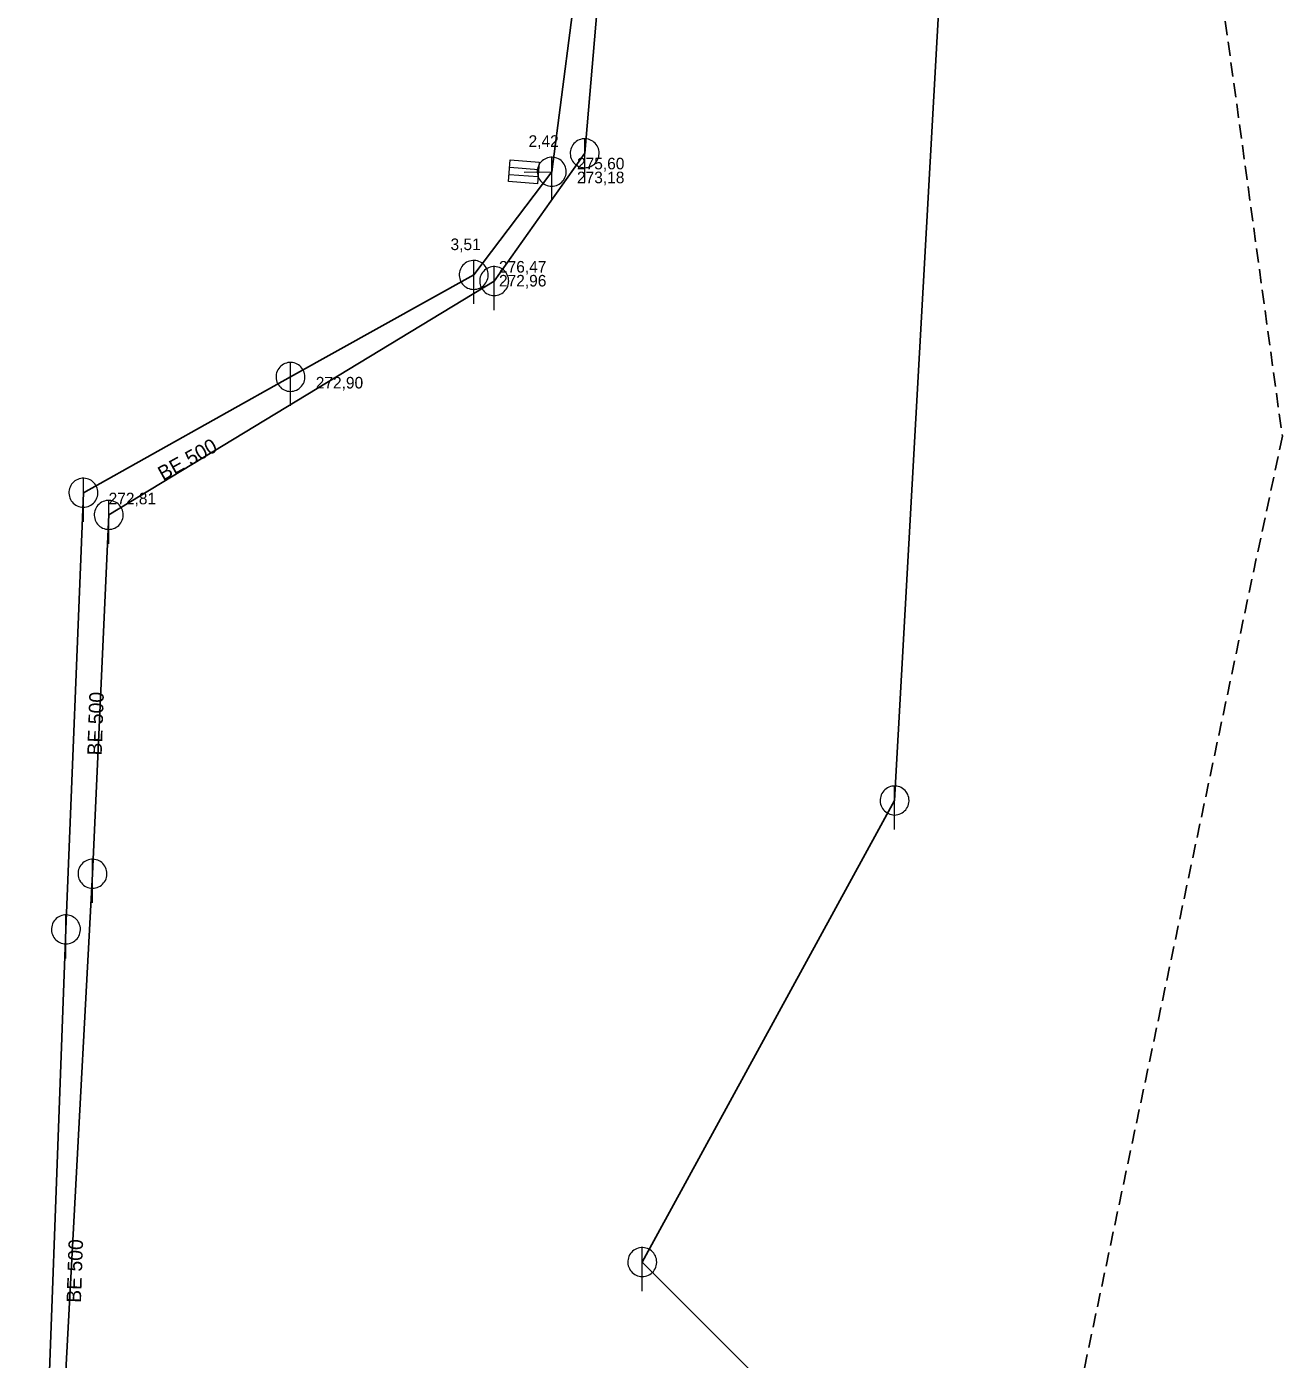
# Model space of a CAD drawing. Extents: x -725153 to -724843, y -978146 to -977794.
# Drawn here: x -724929.4 to -724842.7, y -977983.1 to -977891.1 of the extents above; entities that cross this region are included whole.
import ezdxf

# ---------------------------------------------------------------- set-up
doc = ezdxf.new("R2010")
doc.units = 0
doc.header["$LTSCALE"] = 0.32
doc.linetypes.add('MEDIUM_DASHED', pattern=[4.5, 3, -1.5])
doc.layers.add('1', color=7, linetype='Continuous')
for name, color, linetype, lineweight in [('11', 7, 'Continuous', 13), ('14', 7, 'Continuous', 25), ('22', 7, 'Continuous', 13), ('63', 7, 'MEDIUM_DASHED', 25)]:
    doc.layers.add(name, color=color, linetype=linetype, lineweight=lineweight)

msp = doc.modelspace()

# ---------------------------------------------------------------- linework, layer by layer
at = {"layer": '11'}
msp.add_line((-724895.067, -977901.119), (-724893.153, -977901.096), dxfattribs=at)
at = {"layer": '14'}
for p, q in [((-724887.943, -977865.316), (-724890.881, -977899.822)), ((-724890.881, -977899.822), (-724897.126, -977908.645)), ((-724893.153, -977901.096), (-724898.538, -977908.222)), ((-724897.126, -977908.645), (-724923.729, -977924.789)), ((-724898.538, -977908.222), (-724911.184, -977915.262)), ((-724911.184, -977915.262), (-724925.479, -977923.259)), ((-724925.479, -977923.259), (-724926.682, -977953.405)), ((-724923.729, -977924.789), (-724924.849, -977949.559))]:
    msp.add_line(p, q, dxfattribs=at)
for points in [[(-724873.038, -977838.517), (-724866.293, -977887.198), (-724869.492, -977944.507)], [(-724888.955, -977868.761), (-724891.145, -977885.63), (-724893.153, -977901.096)], [(-724869.492, -977944.507), (-724886.907, -977976.368), (-724871.886, -977991.369), (-724874.269, -978025.195)], [(-724924.849, -977949.559), (-724927.569, -978000.189), (-724927.274, -978049.14)], [(-724926.682, -977953.405), (-724928.359, -977998.839), (-724927.944, -978048.326)]]:
    msp.add_lwpolyline(points, dxfattribs=at)
at = {"layer": '22'}
for p, q in [((-724890.881, -977901.822), (-724890.88, -977898.822)), ((-724893.153, -977903.096), (-724893.152, -977900.096)), ((-724896.093, -977901.286), (-724894.098, -977901.435)), ((-724896.056, -977900.787), (-724894.061, -977900.936)), ((-724898.538, -977910.222), (-724898.537, -977907.222)), ((-724897.126, -977910.645), (-724897.125, -977907.645)), ((-724911.184, -977917.262), (-724911.183, -977914.262)), ((-724925.479, -977925.259), (-724925.478, -977922.259)), ((-724923.729, -977926.789), (-724923.728, -977923.789)), ((-724869.492, -977946.507), (-724869.491, -977943.507)), ((-724924.849, -977951.559), (-724924.848, -977948.559)), ((-724926.682, -977955.405), (-724926.681, -977952.405)), ((-724886.907, -977978.368), (-724886.906, -977975.368))]:
    msp.add_line(p, q, dxfattribs=at)
for points in [[(-724889.881, -977899.822), (-724889.886, -977899.713), (-724889.904, -977899.605), (-724889.934, -977899.499), (-724889.974, -977899.398), (-724890.026, -977899.301), (-724890.088, -977899.211), (-724890.16, -977899.128), (-724890.24, -977899.054), (-724890.328, -977898.988), (-724890.422, -977898.933), (-724890.522, -977898.888), (-724890.627, -977898.855), (-724890.734, -977898.833), (-724890.843, -977898.823), (-724890.953, -977898.825), (-724891.061, -977898.839), (-724891.168, -977898.864), (-724891.271, -977898.901), (-724891.369, -977898.95), (-724891.461, -977899.008), (-724891.547, -977899.077), (-724891.624, -977899.154), (-724891.693, -977899.24), (-724891.752, -977899.332), (-724891.8, -977899.43), (-724891.837, -977899.533), (-724891.863, -977899.64), (-724891.877, -977899.748), (-724891.88, -977899.858), (-724891.87, -977899.967), (-724891.849, -977900.074), (-724891.815, -977900.178), (-724891.771, -977900.278), (-724891.716, -977900.373), (-724891.65, -977900.461), (-724891.576, -977900.541), (-724891.493, -977900.613), (-724891.403, -977900.675), (-724891.307, -977900.727), (-724891.205, -977900.768), (-724891.1, -977900.798), (-724890.992, -977900.816), (-724890.882, -977900.822), (-724890.773, -977900.816), (-724890.665, -977900.798), (-724890.56, -977900.769), (-724890.458, -977900.728), (-724890.361, -977900.676), (-724890.271, -977900.614), (-724890.188, -977900.543), (-724890.113, -977900.463), (-724890.048, -977900.375), (-724889.992, -977900.281), (-724889.948, -977900.181), (-724889.914, -977900.077), (-724889.892, -977899.969), (-724889.882, -977899.86)], [(-724896.018, -977900.289), (-724894.024, -977900.438), (-724894.136, -977901.934), (-724896.13, -977901.785)], [(-724892.153, -977901.096), (-724892.158, -977900.987), (-724892.176, -977900.879), (-724892.206, -977900.773), (-724892.246, -977900.672), (-724892.298, -977900.575), (-724892.36, -977900.485), (-724892.432, -977900.402), (-724892.512, -977900.328), (-724892.6, -977900.262), (-724892.694, -977900.207), (-724892.794, -977900.162), (-724892.899, -977900.129), (-724893.006, -977900.107), (-724893.115, -977900.097), (-724893.225, -977900.099), (-724893.333, -977900.113), (-724893.44, -977900.138), (-724893.543, -977900.175), (-724893.641, -977900.224), (-724893.733, -977900.282), (-724893.819, -977900.351), (-724893.896, -977900.428), (-724893.965, -977900.514), (-724894.024, -977900.606), (-724894.072, -977900.704), (-724894.109, -977900.807), (-724894.135, -977900.914), (-724894.149, -977901.022), (-724894.152, -977901.132), (-724894.142, -977901.241), (-724894.121, -977901.348), (-724894.087, -977901.452), (-724894.043, -977901.552), (-724893.988, -977901.647), (-724893.922, -977901.735), (-724893.848, -977901.815), (-724893.765, -977901.887), (-724893.675, -977901.949), (-724893.579, -977902.001), (-724893.477, -977902.042), (-724893.372, -977902.072), (-724893.264, -977902.09), (-724893.154, -977902.096), (-724893.045, -977902.09), (-724892.937, -977902.072), (-724892.832, -977902.043), (-724892.73, -977902.002), (-724892.633, -977901.95), (-724892.543, -977901.888), (-724892.46, -977901.817), (-724892.385, -977901.737), (-724892.32, -977901.649), (-724892.264, -977901.555), (-724892.22, -977901.455), (-724892.186, -977901.351), (-724892.164, -977901.243), (-724892.154, -977901.134)], [(-724897.538, -977908.222), (-724897.543, -977908.113), (-724897.561, -977908.005), (-724897.591, -977907.899), (-724897.631, -977907.798), (-724897.683, -977907.701), (-724897.745, -977907.611), (-724897.817, -977907.528), (-724897.897, -977907.454), (-724897.985, -977907.388), (-724898.079, -977907.333), (-724898.179, -977907.288), (-724898.284, -977907.255), (-724898.391, -977907.233), (-724898.5, -977907.223), (-724898.61, -977907.225), (-724898.718, -977907.239), (-724898.825, -977907.264), (-724898.928, -977907.301), (-724899.026, -977907.35), (-724899.118, -977907.408), (-724899.204, -977907.477), (-724899.281, -977907.554), (-724899.35, -977907.64), (-724899.409, -977907.732), (-724899.457, -977907.83), (-724899.494, -977907.933), (-724899.52, -977908.04), (-724899.534, -977908.148), (-724899.537, -977908.258), (-724899.527, -977908.367), (-724899.506, -977908.474), (-724899.472, -977908.578), (-724899.428, -977908.678), (-724899.373, -977908.773), (-724899.307, -977908.861), (-724899.233, -977908.941), (-724899.15, -977909.013), (-724899.06, -977909.075), (-724898.964, -977909.127), (-724898.862, -977909.168), (-724898.757, -977909.198), (-724898.649, -977909.216), (-724898.539, -977909.222), (-724898.43, -977909.216), (-724898.322, -977909.198), (-724898.217, -977909.169), (-724898.115, -977909.128), (-724898.018, -977909.076), (-724897.928, -977909.014), (-724897.845, -977908.943), (-724897.77, -977908.863), (-724897.705, -977908.775), (-724897.649, -977908.681), (-724897.605, -977908.581), (-724897.571, -977908.477), (-724897.549, -977908.369), (-724897.539, -977908.26)], [(-724896.126, -977908.645), (-724896.131, -977908.536), (-724896.149, -977908.428), (-724896.179, -977908.322), (-724896.219, -977908.221), (-724896.271, -977908.124), (-724896.333, -977908.034), (-724896.405, -977907.951), (-724896.485, -977907.877), (-724896.573, -977907.811), (-724896.667, -977907.756), (-724896.767, -977907.711), (-724896.872, -977907.678), (-724896.979, -977907.656), (-724897.088, -977907.646), (-724897.198, -977907.648), (-724897.306, -977907.662), (-724897.413, -977907.687), (-724897.516, -977907.724), (-724897.614, -977907.773), (-724897.706, -977907.831), (-724897.792, -977907.9), (-724897.869, -977907.977), (-724897.938, -977908.063), (-724897.997, -977908.155), (-724898.045, -977908.253), (-724898.082, -977908.356), (-724898.108, -977908.463), (-724898.122, -977908.571), (-724898.125, -977908.681), (-724898.115, -977908.79), (-724898.094, -977908.897), (-724898.06, -977909.001), (-724898.016, -977909.101), (-724897.961, -977909.196), (-724897.895, -977909.284), (-724897.821, -977909.364), (-724897.738, -977909.436), (-724897.648, -977909.498), (-724897.552, -977909.55), (-724897.45, -977909.591), (-724897.345, -977909.621), (-724897.237, -977909.639), (-724897.127, -977909.645), (-724897.018, -977909.639), (-724896.91, -977909.621), (-724896.805, -977909.592), (-724896.703, -977909.551), (-724896.606, -977909.499), (-724896.516, -977909.437), (-724896.433, -977909.366), (-724896.358, -977909.286), (-724896.293, -977909.198), (-724896.237, -977909.104), (-724896.193, -977909.004), (-724896.159, -977908.9), (-724896.137, -977908.792), (-724896.127, -977908.683)], [(-724910.184, -977915.262), (-724910.189, -977915.153), (-724910.207, -977915.045), (-724910.237, -977914.939), (-724910.277, -977914.838), (-724910.329, -977914.741), (-724910.391, -977914.651), (-724910.463, -977914.568), (-724910.543, -977914.494), (-724910.631, -977914.428), (-724910.725, -977914.373), (-724910.825, -977914.328), (-724910.93, -977914.295), (-724911.037, -977914.273), (-724911.146, -977914.263), (-724911.256, -977914.265), (-724911.364, -977914.279), (-724911.471, -977914.304), (-724911.574, -977914.341), (-724911.672, -977914.39), (-724911.764, -977914.448), (-724911.85, -977914.517), (-724911.927, -977914.594), (-724911.996, -977914.68), (-724912.055, -977914.772), (-724912.103, -977914.87), (-724912.14, -977914.973), (-724912.166, -977915.08), (-724912.18, -977915.188), (-724912.183, -977915.298), (-724912.173, -977915.407), (-724912.152, -977915.514), (-724912.118, -977915.618), (-724912.074, -977915.718), (-724912.019, -977915.813), (-724911.953, -977915.901), (-724911.879, -977915.981), (-724911.796, -977916.053), (-724911.706, -977916.115), (-724911.61, -977916.167), (-724911.508, -977916.208), (-724911.403, -977916.238), (-724911.295, -977916.256), (-724911.185, -977916.262), (-724911.076, -977916.256), (-724910.968, -977916.238), (-724910.863, -977916.209), (-724910.761, -977916.168), (-724910.664, -977916.116), (-724910.574, -977916.054), (-724910.491, -977915.983), (-724910.416, -977915.903), (-724910.351, -977915.815), (-724910.295, -977915.721), (-724910.251, -977915.621), (-724910.217, -977915.517), (-724910.195, -977915.409), (-724910.185, -977915.3)], [(-724924.479, -977923.259), (-724924.484, -977923.15), (-724924.502, -977923.042), (-724924.532, -977922.936), (-724924.572, -977922.835), (-724924.624, -977922.738), (-724924.686, -977922.648), (-724924.758, -977922.565), (-724924.838, -977922.491), (-724924.926, -977922.425), (-724925.02, -977922.37), (-724925.12, -977922.325), (-724925.225, -977922.292), (-724925.332, -977922.27), (-724925.441, -977922.26), (-724925.551, -977922.262), (-724925.659, -977922.276), (-724925.766, -977922.301), (-724925.869, -977922.338), (-724925.967, -977922.387), (-724926.059, -977922.445), (-724926.145, -977922.514), (-724926.222, -977922.591), (-724926.291, -977922.677), (-724926.35, -977922.769), (-724926.398, -977922.867), (-724926.435, -977922.97), (-724926.461, -977923.077), (-724926.475, -977923.185), (-724926.478, -977923.295), (-724926.468, -977923.404), (-724926.447, -977923.511), (-724926.413, -977923.615), (-724926.369, -977923.715), (-724926.314, -977923.81), (-724926.248, -977923.898), (-724926.174, -977923.978), (-724926.091, -977924.05), (-724926.001, -977924.112), (-724925.905, -977924.164), (-724925.803, -977924.205), (-724925.698, -977924.235), (-724925.59, -977924.253), (-724925.48, -977924.259), (-724925.371, -977924.253), (-724925.263, -977924.235), (-724925.158, -977924.206), (-724925.056, -977924.165), (-724924.959, -977924.113), (-724924.869, -977924.051), (-724924.786, -977923.98), (-724924.711, -977923.9), (-724924.646, -977923.812), (-724924.59, -977923.718), (-724924.546, -977923.618), (-724924.512, -977923.514), (-724924.49, -977923.406), (-724924.48, -977923.297)], [(-724922.729, -977924.789), (-724922.734, -977924.68), (-724922.752, -977924.572), (-724922.782, -977924.466), (-724922.822, -977924.365), (-724922.874, -977924.268), (-724922.936, -977924.178), (-724923.008, -977924.095), (-724923.088, -977924.021), (-724923.176, -977923.955), (-724923.27, -977923.9), (-724923.37, -977923.855), (-724923.475, -977923.822), (-724923.582, -977923.8), (-724923.691, -977923.79), (-724923.801, -977923.792), (-724923.909, -977923.806), (-724924.016, -977923.831), (-724924.119, -977923.868), (-724924.217, -977923.917), (-724924.309, -977923.975), (-724924.395, -977924.044), (-724924.472, -977924.121), (-724924.541, -977924.207), (-724924.6, -977924.299), (-724924.648, -977924.397), (-724924.685, -977924.5), (-724924.711, -977924.607), (-724924.725, -977924.715), (-724924.728, -977924.825), (-724924.718, -977924.934), (-724924.697, -977925.041), (-724924.663, -977925.145), (-724924.619, -977925.245), (-724924.564, -977925.34), (-724924.498, -977925.428), (-724924.424, -977925.508), (-724924.341, -977925.58), (-724924.251, -977925.642), (-724924.155, -977925.694), (-724924.053, -977925.735), (-724923.948, -977925.765), (-724923.84, -977925.783), (-724923.73, -977925.789), (-724923.621, -977925.783), (-724923.513, -977925.765), (-724923.408, -977925.736), (-724923.306, -977925.695), (-724923.209, -977925.643), (-724923.119, -977925.581), (-724923.036, -977925.51), (-724922.961, -977925.43), (-724922.896, -977925.342), (-724922.84, -977925.248), (-724922.796, -977925.148), (-724922.762, -977925.044), (-724922.74, -977924.936), (-724922.73, -977924.827)], [(-724868.492, -977944.507), (-724868.497, -977944.398), (-724868.515, -977944.29), (-724868.545, -977944.184), (-724868.585, -977944.083), (-724868.637, -977943.986), (-724868.699, -977943.896), (-724868.771, -977943.813), (-724868.851, -977943.739), (-724868.939, -977943.673), (-724869.033, -977943.618), (-724869.133, -977943.573), (-724869.238, -977943.54), (-724869.345, -977943.518), (-724869.454, -977943.508), (-724869.564, -977943.51), (-724869.672, -977943.524), (-724869.779, -977943.549), (-724869.882, -977943.586), (-724869.98, -977943.635), (-724870.072, -977943.693), (-724870.158, -977943.762), (-724870.235, -977943.839), (-724870.304, -977943.925), (-724870.363, -977944.017), (-724870.411, -977944.115), (-724870.448, -977944.218), (-724870.474, -977944.325), (-724870.488, -977944.433), (-724870.491, -977944.543), (-724870.481, -977944.652), (-724870.46, -977944.759), (-724870.426, -977944.863), (-724870.382, -977944.963), (-724870.327, -977945.058), (-724870.261, -977945.146), (-724870.187, -977945.226), (-724870.104, -977945.298), (-724870.014, -977945.36), (-724869.918, -977945.412), (-724869.816, -977945.453), (-724869.711, -977945.483), (-724869.603, -977945.501), (-724869.493, -977945.507), (-724869.384, -977945.501), (-724869.276, -977945.483), (-724869.171, -977945.454), (-724869.069, -977945.413), (-724868.972, -977945.361), (-724868.882, -977945.299), (-724868.799, -977945.228), (-724868.724, -977945.148), (-724868.659, -977945.06), (-724868.603, -977944.966), (-724868.559, -977944.866), (-724868.525, -977944.762), (-724868.503, -977944.654), (-724868.493, -977944.545)], [(-724923.849, -977949.559), (-724923.854, -977949.45), (-724923.872, -977949.342), (-724923.902, -977949.236), (-724923.942, -977949.135), (-724923.994, -977949.038), (-724924.056, -977948.948), (-724924.128, -977948.865), (-724924.208, -977948.791), (-724924.296, -977948.725), (-724924.39, -977948.67), (-724924.49, -977948.625), (-724924.595, -977948.592), (-724924.702, -977948.57), (-724924.811, -977948.56), (-724924.921, -977948.562), (-724925.029, -977948.576), (-724925.136, -977948.601), (-724925.239, -977948.638), (-724925.337, -977948.687), (-724925.429, -977948.745), (-724925.515, -977948.814), (-724925.592, -977948.891), (-724925.661, -977948.977), (-724925.72, -977949.069), (-724925.768, -977949.167), (-724925.805, -977949.27), (-724925.831, -977949.377), (-724925.845, -977949.485), (-724925.848, -977949.595), (-724925.838, -977949.704), (-724925.817, -977949.811), (-724925.783, -977949.915), (-724925.739, -977950.015), (-724925.684, -977950.11), (-724925.618, -977950.198), (-724925.544, -977950.278), (-724925.461, -977950.35), (-724925.371, -977950.412), (-724925.275, -977950.464), (-724925.173, -977950.505), (-724925.068, -977950.535), (-724924.96, -977950.553), (-724924.85, -977950.559), (-724924.741, -977950.553), (-724924.633, -977950.535), (-724924.528, -977950.506), (-724924.426, -977950.465), (-724924.329, -977950.413), (-724924.239, -977950.351), (-724924.156, -977950.28), (-724924.081, -977950.2), (-724924.016, -977950.112), (-724923.96, -977950.018), (-724923.916, -977949.918), (-724923.882, -977949.814), (-724923.86, -977949.706), (-724923.85, -977949.597)], [(-724925.682, -977953.405), (-724925.687, -977953.296), (-724925.705, -977953.188), (-724925.735, -977953.082), (-724925.775, -977952.981), (-724925.827, -977952.884), (-724925.889, -977952.794), (-724925.961, -977952.711), (-724926.041, -977952.637), (-724926.129, -977952.571), (-724926.223, -977952.516), (-724926.323, -977952.471), (-724926.428, -977952.438), (-724926.535, -977952.416), (-724926.644, -977952.406), (-724926.754, -977952.408), (-724926.862, -977952.422), (-724926.969, -977952.447), (-724927.072, -977952.484), (-724927.17, -977952.533), (-724927.262, -977952.591), (-724927.348, -977952.66), (-724927.425, -977952.737), (-724927.494, -977952.823), (-724927.553, -977952.915), (-724927.601, -977953.013), (-724927.638, -977953.116), (-724927.664, -977953.223), (-724927.678, -977953.331), (-724927.681, -977953.441), (-724927.671, -977953.55), (-724927.65, -977953.657), (-724927.616, -977953.761), (-724927.572, -977953.861), (-724927.517, -977953.956), (-724927.451, -977954.044), (-724927.377, -977954.124), (-724927.294, -977954.196), (-724927.204, -977954.258), (-724927.108, -977954.31), (-724927.006, -977954.351), (-724926.901, -977954.381), (-724926.793, -977954.399), (-724926.683, -977954.405), (-724926.574, -977954.399), (-724926.466, -977954.381), (-724926.361, -977954.352), (-724926.259, -977954.311), (-724926.162, -977954.259), (-724926.072, -977954.197), (-724925.989, -977954.126), (-724925.914, -977954.046), (-724925.849, -977953.958), (-724925.793, -977953.864), (-724925.749, -977953.764), (-724925.715, -977953.66), (-724925.693, -977953.552), (-724925.683, -977953.443)], [(-724885.907, -977976.368), (-724885.912, -977976.259), (-724885.93, -977976.151), (-724885.96, -977976.045), (-724886, -977975.944), (-724886.052, -977975.847), (-724886.114, -977975.757), (-724886.186, -977975.674), (-724886.266, -977975.6), (-724886.354, -977975.534), (-724886.448, -977975.479), (-724886.548, -977975.434), (-724886.653, -977975.401), (-724886.76, -977975.379), (-724886.869, -977975.369), (-724886.979, -977975.371), (-724887.087, -977975.385), (-724887.194, -977975.41), (-724887.297, -977975.447), (-724887.395, -977975.496), (-724887.487, -977975.554), (-724887.573, -977975.623), (-724887.65, -977975.7), (-724887.719, -977975.786), (-724887.778, -977975.878), (-724887.826, -977975.976), (-724887.863, -977976.079), (-724887.889, -977976.186), (-724887.903, -977976.294), (-724887.906, -977976.404), (-724887.896, -977976.513), (-724887.875, -977976.62), (-724887.841, -977976.724), (-724887.797, -977976.824), (-724887.742, -977976.919), (-724887.676, -977977.007), (-724887.602, -977977.087), (-724887.519, -977977.159), (-724887.429, -977977.221), (-724887.333, -977977.273), (-724887.231, -977977.314), (-724887.126, -977977.344), (-724887.018, -977977.362), (-724886.908, -977977.368), (-724886.799, -977977.362), (-724886.691, -977977.344), (-724886.586, -977977.315), (-724886.484, -977977.274), (-724886.387, -977977.222), (-724886.297, -977977.16), (-724886.214, -977977.089), (-724886.139, -977977.009), (-724886.074, -977976.921), (-724886.018, -977976.827), (-724885.974, -977976.727), (-724885.94, -977976.623), (-724885.918, -977976.515), (-724885.908, -977976.406)]]:
    msp.add_lwpolyline(points, close=True, dxfattribs=at)
at = {"layer": '63'}
msp.add_lwpolyline([(-725126.038, -977904.704), (-725126.038, -977794.451), (-724874.829, -977812.594), (-724855.29, -977827.945), (-724842.73, -977919.358), (-724859.477, -977998.21), (-724911.114, -978092.413), (-724961.356, -978146.144), (-725152.554, -978126.605)], close=True, dxfattribs=at)

# ---------------------------------------------------------------- texts
at = {"layer": '1'}
for s, p in [('2,42', (-724894.753, -977899.384)), ('3,51', (-724900.138, -977906.51))]:
    msp.add_text(s, height=0.8, dxfattribs=at).set_placement(p)
for rotation, p in [(29, (-724919.98, -977922.457)), (88, (-724924.216, -977941.408)), (88, (-724925.646, -977979.192))]:
    msp.add_text('BE 500', height=1, rotation=rotation, dxfattribs=at).set_placement(p)
at = {"layer": '22'}
for s, p in [('275,60', (-724891.41, -977900.935)), ('273,18', (-724891.41, -977901.895)), ('276,47', (-724896.795, -977908.062)), ('272,96', (-724896.795, -977909.022)), ('272,90', (-724909.441, -977916.062)), ('272,81', (-724923.736, -977924.058))]:
    msp.add_text(s, height=0.8, dxfattribs=at).set_placement(p)

doc.saveas('drawing.dxf')
